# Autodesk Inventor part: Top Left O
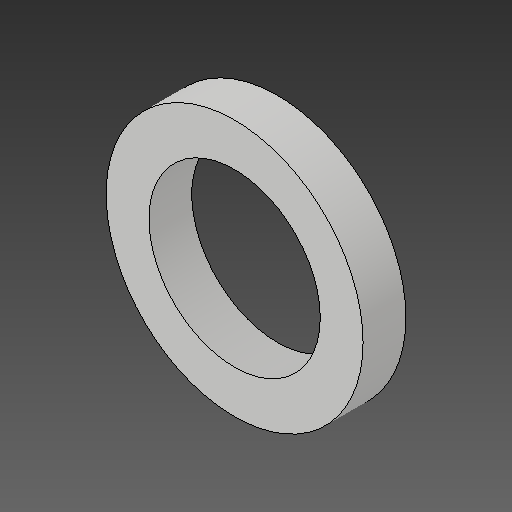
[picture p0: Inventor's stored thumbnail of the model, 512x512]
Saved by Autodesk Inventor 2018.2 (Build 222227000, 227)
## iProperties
Created: 2018-03
Part Number: Top Left O
Material: Generic
Document SubType Name: Modeling
Designer: PeterMaxwell-Stewart
Mass: 1.9635 g
Surface Area: 15.708 cm^2
Volume: 1.9635 cm^3
Density: 1 g/cm^3
Appearance: Default
Author: PeterMaxwell-Stewart
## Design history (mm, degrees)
derived "O's and X's.ipt"
feature "Top Left O::O's and X's.ipt" dims "d0" = 10
tag "TaggingFeature1"
body "Solid1"
